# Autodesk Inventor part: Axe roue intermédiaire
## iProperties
Created: 2001-06
Part Number: Axe roue intermédiaire
Material: Par défaut
Document SubType Name: Modélisation
Designer: Flavien MARTY
Control State: 0
Master: False
Checked Out: False
Shininess: 25.0
Length Units: 11269
Angle Units: 11279
Time Units: 11290
Mass Units: 11283
Length Display Precision: 3
Angle Display Precision: 2
Compacted: True
Density: 0.0
Volumn: 0.0
Area: 0.0
PropertySet Name: Model Information
Author: Flavien MARTY
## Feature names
1. Extrusion1
2. Extrusion2
